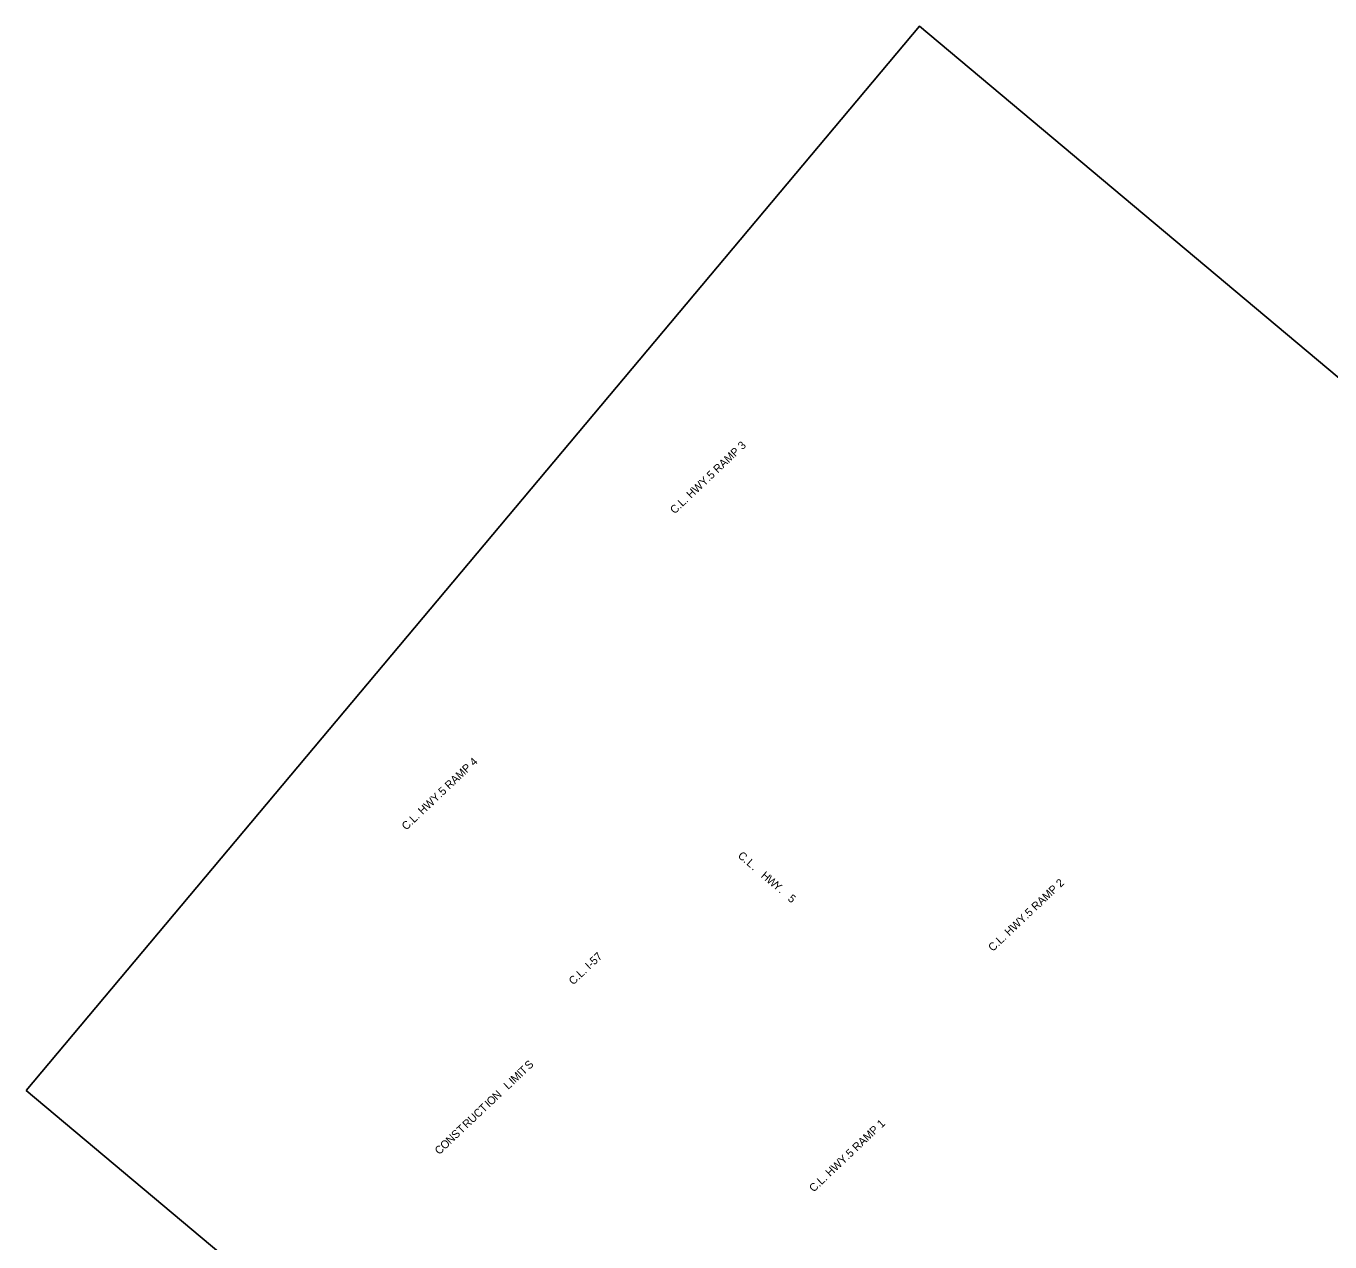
# Model space of a CAD drawing. Extents: x 1292584 to 1294692, y 222754 to 224578.
# Drawn here: x 1292584 to 1293562, y 223666 to 224578 of the extents above; entities that cross this region are included whole.
import ezdxf

# ---------------------------------------------------------------- set-up
doc = ezdxf.new("R2010")
doc.units = 0
doc.layers.add('1', color=7, linetype='Continuous')
doc.layers.add('R_Striping', color=7, linetype='Continuous')

msp = doc.modelspace()

# ---------------------------------------------------------------- linework, layer by layer
at = {"layer": '1'}
msp.add_lwpolyline([(1292584.05, 223779.83), (1293254.04, 224578.3), (1294171.77, 223808.23), (1294139.92, 223770.28), (1294291.79, 223642.84), (1294281.83, 223630.97), (1294336.68, 223584.95), (1294241.87, 223471.95), (1294339.54, 223390), (1293806.17, 222754.35)], close=True, dxfattribs=at)
msp.add_lwpolyline([(1292584.05, 223779.83), (1293254.04, 224578.3), (1294171.77, 223808.23), (1294139.92, 223770.28), (1294291.79, 223642.84), (1294281.83, 223630.97), (1294336.68, 223584.95), (1294241.87, 223471.95), (1294339.54, 223390), (1293806.17, 222754.35)], close=True, dxfattribs=at)
msp.add_lwpolyline([(1292584.05, 223779.83), (1293254.04, 224578.3), (1294171.77, 223808.23), (1294139.92, 223770.28), (1294291.79, 223642.84), (1294281.83, 223630.97), (1294336.68, 223584.95), (1294241.87, 223471.95), (1294339.54, 223390), (1293806.17, 222754.35)], close=True, dxfattribs=at)
msp.add_lwpolyline([(1292584.05, 223779.83), (1293254.04, 224578.3), (1294171.77, 223808.23), (1294139.92, 223770.28), (1294291.79, 223642.84), (1294281.83, 223630.97), (1294336.68, 223584.95), (1294241.87, 223471.95), (1294339.54, 223390), (1293806.17, 222754.35)], close=True, dxfattribs=at)
msp.add_lwpolyline([(1292584.05, 223779.83), (1293254.04, 224578.3), (1294171.77, 223808.23), (1294139.92, 223770.28), (1294291.79, 223642.84), (1294281.83, 223630.97), (1294336.68, 223584.95), (1294241.87, 223471.95), (1294339.54, 223390), (1293806.17, 222754.35)], close=True, dxfattribs=at)
msp.add_lwpolyline([(1292584.05, 223779.83), (1293254.04, 224578.3), (1294171.77, 223808.23), (1294139.92, 223770.28), (1294291.79, 223642.84), (1294281.83, 223630.97), (1294336.68, 223584.95), (1294241.87, 223471.95), (1294339.54, 223390), (1293806.17, 222754.35)], close=True, dxfattribs=at)

# ---------------------------------------------------------------- texts
at = {"layer": 'R_Striping'}
for s, rotation, p in [('C.L. HWY.5 RAMP 3', 43.44102, (1293070.34, 224211.98)), ('C.L. HWY.5 RAMP 4', 43.44102, (1292869.09, 223974.78)), ('C', 319.35201, (1293117.25, 223955.22)), ('.', 319.35201, (1293121.55, 223951.52)), ('L', 319.35201, (1293123.77, 223949.61)), ('.', 319.35201, (1293127.86, 223946.11)), ('H', 319.35201, (1293134.63, 223940.29)), ('W', 319.35201, (1293138.72, 223936.78)), ('C.L. HWY.5 RAMP 2', 43.44102, (1293308.9, 223883.8)), ('Y', 319.35201, (1293143.59, 223932.6)), ('.', 319.35201, (1293147.97, 223928.84)), ('5', 319.35201, (1293154.74, 223923.02)), ('C.L. I-57', 43.46361, (1292994.33, 223858.69)), ('S', 43.5814, (1292961.24, 223795.22)), ('M', 43.5814, (1292950.9, 223785.38)), ('I', 43.5814, (1292955.56, 223789.81)), ('T', 43.5814, (1292957, 223791.18)), ('L', 43.62142, (1292945.57, 223780.3)), ('I', 43.5814, (1292949.47, 223784.01)), ('I', 43.2129, (1292931.33, 223766.9)), ('O', 43.2129, (1292932.77, 223768.26)), ('N', 43.26684, (1292937.05, 223772.28)), ('U', 43.46841, (1292918.79, 223755.03)), ('C', 43.46841, (1292922.97, 223759)), ('T', 43.46841, (1292927.09, 223762.9)), ('T', 43.50284, (1292910.42, 223747.11)), ('R', 43.36145, (1292914.66, 223751.13)), ('C.L. HWY.5 RAMP 1', 43.44102, (1293174.62, 223703.31)), ('O', 43.65543, (1292897.99, 223735.25)), ('N', 43.65543, (1292902.23, 223739.29)), ('S', 43.65543, (1292906.33, 223743.21)), ('C', 43.37806, (1292893.85, 223731.33))]:
    msp.add_text(s, height=6, rotation=rotation, dxfattribs=at).set_placement(p)

doc.saveas('drawing.dxf')
